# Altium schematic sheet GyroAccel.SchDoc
size A; SheetNumber: roneV11-GyroAccel; SheetTotal: 6
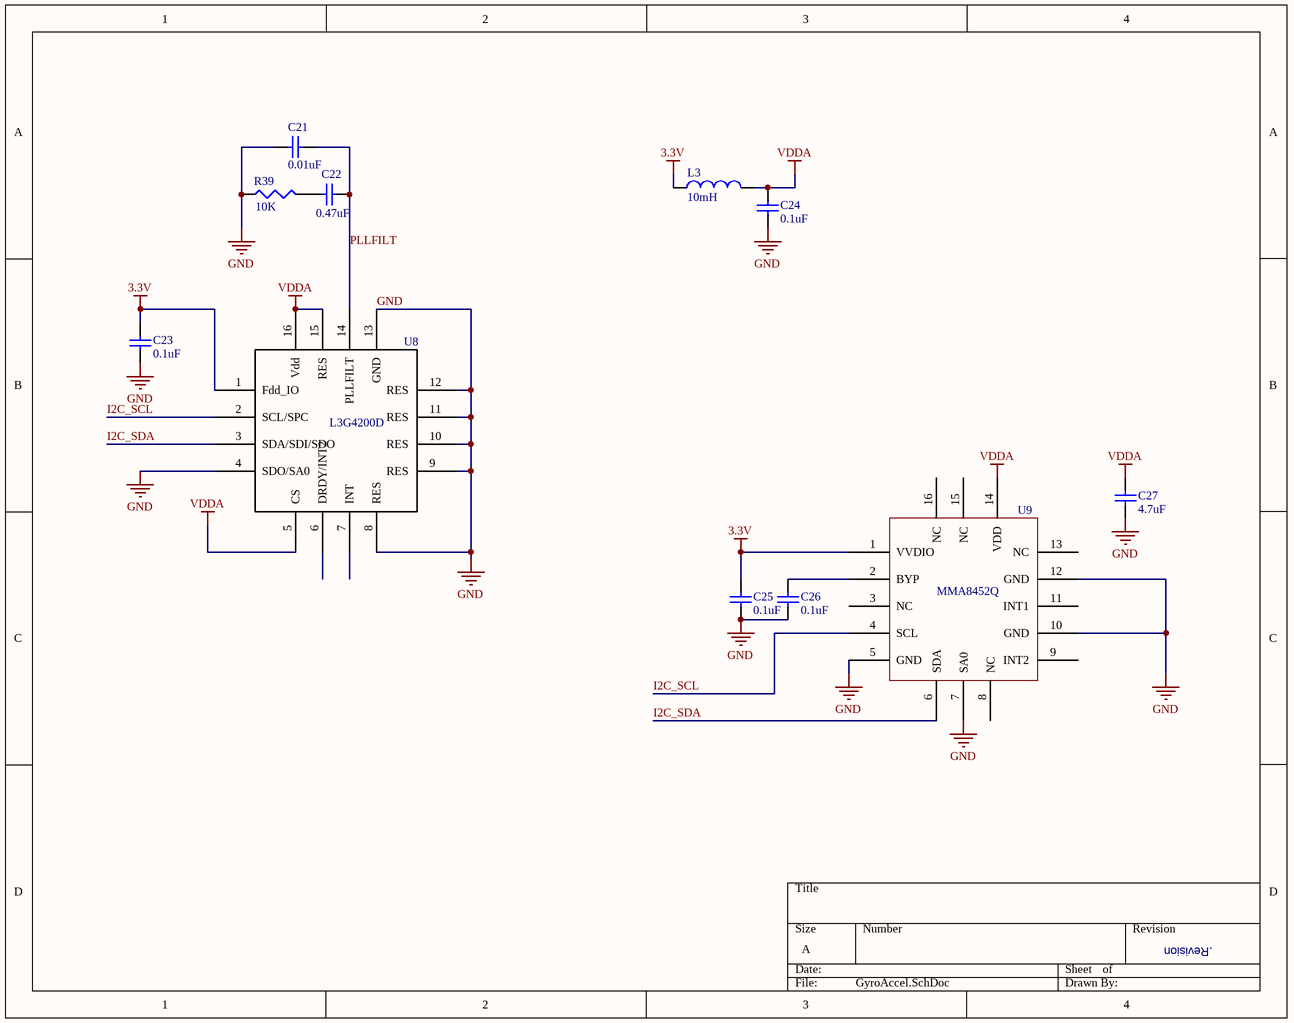
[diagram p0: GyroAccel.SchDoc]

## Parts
C21  value 0.01uF  [CAPC1005L]  (hidden comment: Cap Semi)
C22  value 0.47uF  [CAPC1005L]  (hidden comment: Cap Semi)
C23  value 0.1uF  [CAPC1005L]  (hidden comment: Cap Semi)
C24  value 0.1uF  [CAPC1005L]  (hidden comment: Cap Semi)
C25  value 0.1uF  [CAPC1005L]  (hidden comment: Cap Semi)
C26  value 0.1uF  [CAPC1005L]  (hidden comment: Cap Semi)
C27  value 4.7uF  [CAPC1608L]  (hidden comment: Cap Semi)
L3  value 10mH  [INDC2012L]  (hidden comment: Inductor)
R39  value 10K  [RESC1608L]  (hidden comment: Res3)
U8  L3G4200D  [L3G2004D]
U9  MMA8452Q  [MMA8452Q]

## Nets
3.3V: C23.2 C25.2 L3.2 U8.1(Fdd_IO) U9.1(VVDIO)
GND: C21.2 C23.1 C24.1 C25.1 C26.1 C27.1 R39.1 U8.4(SDO/SA0) U8.8(RES) U8.9(RES) U8.10(RES) U8.11(RES) U8.12(RES) U8.13(GND) U9.5(GND) U9.7(SA0) U9.10(GND) U9.12(GND)
VDDA: C24.2 C27.2 L3.1 U8.5(CS) U8.15(RES) U8.16(Vdd) U9.14(VDD)
I2C_SCL: U8.2(SCL/SPC) U9.4(SCL)
I2C_SDA: U8.3(SDA/SDI/SDO) U9.6(SDA)
PLLFILT: C21.1 C22.1 U8.14(PLLFILT)
NetC22_2: C22.2 R39.2
NetC26_2: C26.2 U9.2(BYP)

Not connected (* = marked no-connect by the designer): U8 6(DRDY/INT2) 7(INT); U9 3(NC) 8(NC) 9(INT2) 11(INT1) 13(NC) 15(NC) 16(NC)

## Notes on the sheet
- .Revision

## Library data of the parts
C21 = Cap Semi: Capacitor (Semiconductor SIM Model); Part Number: UMK105B7103KV-F; Manufacturer: Taiyo Yuden
C22 = Cap Semi: Capacitor (Semiconductor SIM Model); Part Number: GRM155F51C474ZA01D; Manufacturer: Murata
C23-C26 = Cap Semi: Capacitor (Semiconductor SIM Model); Part Number: GRM155R71C104KA88D; Manufacturer: Murata
C27 = Cap Semi: Capacitor (Semiconductor SIM Model); Part Number: JMK107BJ475KA-T; Manufacturer: Taiyo Yuden
L3 = Inductor: Part Number: MMZ2012R102A; Manufacturer: TDK; Code_IEC: 1005
R39 = Res3: Resistor; Part Number: 71-CRCW0603-10K-E3; Manufacturer: Vishay Dale
U8 = L3G4200D: 3axis gyroscope, SPI; Part Number: L3G4200DTR; Manufacturer: ST Mircoelectronics
U9 = MMA8452Q: Part Number: MMA8452QT; Manufacturer: Freescale Semiconductor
